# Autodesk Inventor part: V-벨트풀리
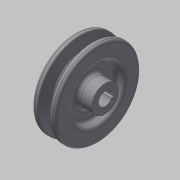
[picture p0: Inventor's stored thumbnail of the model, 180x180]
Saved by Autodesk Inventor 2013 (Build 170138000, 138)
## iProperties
Created: 2015-02
Part Number: V-벨트풀리
Material: 일반
Document SubType Name: Modeling
Designer: Administrator
Density: 1 g/cm^3
Author: Administrator
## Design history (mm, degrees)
sketch "스케치1"
  geometry: L1 (0, 0)-(25, 0); L2 (0, 5.5)-(25, 5.5); L3 (25, 5.5)-(25, 11); L4 (25, 11)-(13, 11); L5 (9.5, 0)-(9.5, 32.5); L6 (13, 11)-(13, 21.5); L7 (13, 21.5)-(19, 21.5); L8 (19, 21.5)-(19, 32.5); L9 (19, 32.5)-(19, 35.2); L10 (19, 35.2)-(14.325, 35.2); L11 (14.325, 35.2)-(13.5, 32.5); L12 (13.5, 32.5)-(11.574, 26.2); L13 (11.574, 26.2)-(9.5, 26.2); L14 (7.426, 26.2)-(9.5, 26.2); L15 (5.5, 32.5)-(7.426, 26.2); L16 (4.675, 35.2)-(5.5, 32.5); L17 (0, 35.2)-(4.675, 35.2); L18 (0, 32.5)-(0, 35.2); L19 (0, 21.5)-(0, 32.5); L20 (6, 21.5)-(0, 21.5); L21 (6, 11)-(6, 21.5); L22 (6, 11)-(0, 11); L23 (0, 11)-(0, 5.5); 3 further points
  constraints: 46 end point, 9 perpendicular, 8 symmetric about line, 3 midpoint, 3 vertical alignment, 2 collinear, 2 parallel, 2 point on line, 1 horizontal, 1 horizontal alignment
  dimensions: "d0" = 25 distance of L1.start L1.end; "d1" = 11 diameter of L2 L1; "d2" = 22 diameter of L4 L1; "d3" = 32.5 distance of L5.start L5.end; "d4" = 8 distance of L11.end L15.start; "d5" = 34 deg angle of L15 L12; "d6" = 19 distance between parallel lines of L19 L8; "d7" = 6 distance between parallel lines of L19 L21; "d8" = 43 diameter of L20 L1; "d9" = 2.7 distance from line of L10 L11.end; "d10" = 6.3 distance from line of L11.end L13
revolve "회전1" sketch "스케치1" stored, may be unused: angle "d11" = 90 deg
fillet "모깎기1" dims "d12" = 0.5, "d13" = 2, "d14" = 1
fillet "모깎기2" dims "d15" = 3
sketch "스케치2"
  geometry: L1 (-2, 0)-(2, 0); L2 (2, 0)-(2, 7.3); L3 (2, 7.3)-(-2, 7.3); L4 (-2, 7.3)-(-2, 0); C1 r 5.5 at (0, 0) reference; 1 further point
  constraints: 8 end point, 2 parallel, 1 coincident, 1 horizontal, 1 midpoint, 1 perpendicular
  dimensions: "d16" = 4 distance of L2.end L3.end; "d18" = 7.3 distance from line of L3 C1.centre
extrude "돌출1" cut sketch "스케치2" stored distance "d19" = 10; taper "d20" = 0 deg
node "솔리드1"
